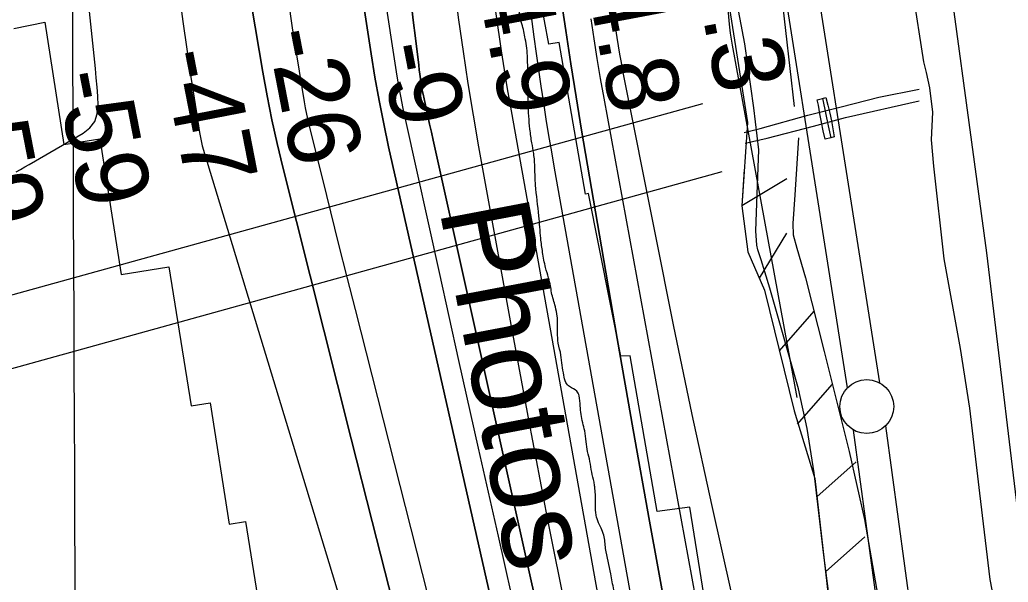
# Model space of a CAD drawing. Extents: x 3419139 to 3457078, y 540382 to 565875.
# Drawn here: x 3439010 to 3439927, y 554398 to 554920 of the extents above; entities that cross this region are included whole.
import ezdxf

# ---------------------------------------------------------------- set-up
doc = ezdxf.new("R2010")
doc.units = 0
for name, color, linetype in [('V-BRDG-OTLN', 7, 'Continuous'), ('V-FLOD-BASE', 7, 'Continuous'), ('V-GRID-MAJR', 7, 'Continuous'), ('V-LEVE-TOET', 7, 'Continuous'), ('V-RIVR-EDGE', 7, 'Continuous'), ('V-RIVR-IDEN', 7, 'Continuous'), ('V-RIVR-RANG', 7, 'Continuous'), ('V-ROAD-CNTR', 7, 'Continuous'), ('V-RRAP-FSHR', 7, 'Continuous'), ('V-RRAP-RVMT', 7, 'Continuous'), ('V-SURV-LINE', 7, 'Continuous'), ('V-TOPO-DPTH', 7, 'Continuous'), ('V-TOPO-MAJR', 7, 'Continuous'), ('V-TOPO-MINR', 7, 'Continuous'), ('V-TOPO-WATR', 7, 'Continuous'), ('V-UTIL-LINE', 7, 'Continuous')]:
    doc.layers.add(name, color=color, linetype=linetype)

msp = doc.modelspace()

# ---------------------------------------------------------------- linework, layer by layer
at = {"layer": 'V-BRDG-OTLN'}
msp.add_lwpolyline([(3439749.87, 554845.8), (3439754.63, 554847.01), (3439757.82, 554847.83), (3439759.7, 554840.62), (3439761.41, 554833.37), (3439762.93, 554826.08), (3439764.28, 554818.75), (3439765.44, 554811.4), (3439762.43, 554810.57), (3439757.26, 554809.14), (3439755.44, 554817.01), (3439753.79, 554824.91), (3439752.31, 554832.84), (3439750.99, 554840.8)], close=True, dxfattribs=at)
msp.add_lwpolyline([(3439754.63, 554847.01), (3439754.86, 554845.79), (3439757.33, 554833.62), (3439759.95, 554821.47), (3439762.43, 554810.57)], dxfattribs=at)
at = {"layer": 'V-FLOD-BASE'}
for points in [[(3439602.39, 555940.97), (3439610.62, 555860.66), (3439621.65, 555775.29), (3439629.34, 555701.72), (3439639.26, 555619.16), (3439647.18, 555526.78), (3439660.71, 555427.09), (3439668.04, 555323.21), (3439677.09, 555228.58), (3439688.38, 555137.32), (3439702.48, 555045.2), (3439712.16, 554980.61), (3439720.42, 554909.85), (3439728.39, 554839.37)], [(3439732.26, 554810.44), (3439729.04, 554757.67), (3439727.3, 554731.01), (3439727.56, 554720.62), (3439730.89, 554708.26), (3439738.97, 554680.73), (3439756.22, 554612.19), (3439779.58, 554519.49), (3439793.75, 554456.58), (3439805.94, 554385.24), (3439813.65, 554321.78), (3439825.79, 554230.52), (3439838.21, 554139.53), (3439850.64, 554050.23), (3439861.12, 553972.72), (3439871.35, 553905.32)]]:
    msp.add_lwpolyline(points, dxfattribs=at)
at = {"layer": 'V-GRID-MAJR'}
msp.add_spline([(3439098.77, 545841.13), (3439072.33, 551898.65), (3439045.89, 557959.64), (3439019.44, 564020.65), (3439019.42, 564024.1)], degree=3, dxfattribs=at)
at = {"layer": 'V-LEVE-TOET'}
for points in [[(3439831.14, 553904.45), (3439824, 553965.54), (3439807.98, 554065.87), (3439797.52, 554142.09), (3439784.54, 554226.44), (3439774.35, 554298.74), (3439763.02, 554368.52), (3439755.6, 554425.97), (3439747.08, 554499.67), (3439740.46, 554540.86), (3439732.42, 554577.58), (3439715.19, 554638.69), (3439705.74, 554670.93), (3439701.02, 554686.07), (3439697.68, 554697.28), (3439694.62, 554706.53), (3439693.79, 554711.01), (3439692.7, 554724.18), (3439694.18, 554758.08), (3439695.68, 554799.26), (3439691, 554838.2), (3439682.74, 554897.61), (3439664.2, 554994.02)], [(3439838.15, 554946.85), (3439848.36, 554881), (3439850.86, 554871.19), (3439853.91, 554856.89), (3439856.66, 554834.2), (3439855.48, 554808.7), (3439857.66, 554784.05), (3439867.27, 554698.3), (3439882.48, 554615.07), (3439891.04, 554559.86), (3439900.38, 554480.84), (3439910, 554400.98), (3439924.39, 554327.55), (3439935.64, 554224.99)]]:
    msp.add_lwpolyline(points, dxfattribs=at)
at = {"layer": 'V-RIVR-EDGE'}
for points in [[(3439543.91, 554480), (3439543.32, 554486.69), (3439542.62, 554491.27), (3439540.53, 554500.44), (3439538.8, 554510.31), (3439536.7, 554519.47), (3439535.32, 554528.64), (3439533.93, 554538.86), (3439532.19, 554546.27), (3439529.76, 554561.78), (3439528.73, 554571.29), (3439526.62, 554575.53), (3439519.94, 554579.77), (3439516.43, 554583.66), (3439514.68, 554590.36), (3439512.94, 554599.52), (3439511.91, 554609.04), (3439509.47, 554619.97), (3439508.79, 554629.84), (3439508.81, 554638.65), (3439508.47, 554644.99), (3439506.73, 554653.8), (3439503.24, 554666.85), (3439502.2, 554673.19), (3439500.46, 554680.6), (3439497.66, 554690.12), (3439494.88, 554704.22), (3439493.15, 554717.26), (3439491.44, 554738.06), (3439488.34, 554766.61), (3439487.67, 554782.47), (3439486.65, 554795.86), (3439484.91, 554805.73), (3439483.18, 554818.42), (3439481.48, 554842.74), (3439481.52, 554860), (3439481.19, 554870.93), (3439480.87, 554884.32), (3439480.19, 554893.48), (3439478.8, 554902.3), (3439475.67, 554916.05), (3439473.57, 554924.51), (3439473.58, 554928.03), (3439475.36, 554932.61), (3439475.36, 554936.13), (3439473.96, 554938.96), (3439472.21, 554942.84), (3439468.7, 554949.54), (3439467.66, 554955.53), (3439467.67, 554961.52), (3439467, 554972.45), (3439467.01, 554977.38), (3439467.02, 554983.37), (3439465.97, 554986.55), (3439461.77, 554994.66), (3439459.32, 555002.77), (3439456.9, 555022.51), (3439457.63, 555031.67), (3439457.64, 555035.55), (3439456.94, 555039.78), (3439454.14, 555047.18), (3439453.1, 555052.82), (3439453.11, 555056), (3439454.53, 555059.16), (3439453.14, 555068.33), (3439453.86, 555076.08), (3439453.52, 555080.66), (3439450.39, 555096.17), (3439448.68, 555116.26), (3439447.65, 555127.54), (3439446.25, 555134.24), (3439444.5, 555138.47), (3439444.51, 555141.64), (3439444.52, 555145.52), (3439443.13, 555152.22), (3439438.59, 555168.44), (3439435.44, 555180.08), (3439433, 555189.24), (3439430.55, 555195.24), (3439427.41, 555209.69), (3439426.07, 555235.42), (3439423.3, 555257.98), (3439423.34, 555271.02), (3439423.35, 555275.95), (3439425.12, 555280.18), (3439424.78, 555283.7), (3439423.06, 555303.08), (3439422.03, 555311.9), (3439421.02, 555332.34), (3439420.69, 555340.79)], [(3439897.96, 552838.81), (3439895.18, 552852.91), (3439892.04, 552868.07), (3439889.26, 552883.93), (3439888.92, 552888.51), (3439886.81, 552890.99), (3439885.41, 552893.46), (3439884.71, 552896.28), (3439883.69, 552908.96), (3439881.25, 552919.89), (3439878.81, 552931.18), (3439877.42, 552939.99), (3439873.94, 552955.15), (3439875, 552957.61), (3439875.01, 552962.55), (3439873.97, 552969.24), (3439873.63, 552972.77), (3439870.47, 552980.18), (3439865.91, 552986.88), (3439863.81, 552992.53), (3439861.36, 552999.93), (3439860.32, 553005.57), (3439858.57, 553011.92), (3439857.18, 553017.91), (3439855.43, 553023.91), (3439852.28, 553031.32), (3439848.77, 553037.32), (3439845.62, 553045.08), (3439842.12, 553056.71), (3439838.28, 553071.17), (3439833.75, 553092.32), (3439828.87, 553114.18), (3439822.92, 553128.29), (3439821.87, 553133.93), (3439821.89, 553141.33), (3439820.5, 553150.5), (3439817.01, 553162.14), (3439815.97, 553169.89), (3439815.3, 553181.87), (3439812.88, 553202.32), (3439811.84, 553208.31), (3439810.44, 553213.6), (3439806.59, 553223.12), (3439803.44, 553233), (3439801.01, 553245.69), (3439798.2, 553251.33), (3439796.45, 553255.21), (3439794.35, 553261.56), (3439791.93, 553279.19), (3439786.69, 553298.23), (3439783.91, 553315.15), (3439782.87, 553320.08), (3439780.07, 553329.96), (3439779.04, 553338.42), (3439778, 553346.17), (3439774.51, 553358.87), (3439769.61, 553372.27), (3439764.01, 553387.79), (3439758.06, 553404.36), (3439752.81, 553419.53), (3439741.6, 553446.34), (3439736.69, 553454.1), (3439731.43, 553464.68), (3439730.38, 553469.97), (3439729.69, 553476.67), (3439729.72, 553486.54), (3439729.02, 553489), (3439726.91, 553492.18), (3439726.23, 553498.88), (3439724.85, 553513.68), (3439721.37, 553531.31), (3439717.55, 553552.81), (3439712.31, 553570.44), (3439710.22, 553579.61), (3439708.49, 553593.71), (3439705.02, 553614.16), (3439704.68, 553622.26), (3439704.69, 553626.49), (3439708.58, 553631.06), (3439711.06, 553635.28), (3439710.71, 553638.81), (3439709.32, 553643.75), (3439705.8, 553645.87), (3439697.71, 553653.64), (3439695.61, 553658.93), (3439695.27, 553664.92), (3439694.61, 553680.43), (3439696.73, 553685.01), (3439699.56, 553689.23), (3439699.22, 553692.75), (3439697.12, 553699.8), (3439696.09, 553710.03), (3439696.11, 553716.37), (3439695.45, 553735.75), (3439695.83, 553748.79), (3439695.16, 553762.53), (3439697.64, 553766.75), (3439697.65, 553771.33), (3439696.97, 553779.09), (3439694.87, 553788.26), (3439690.34, 553807.65), (3439684.39, 553823.52), (3439683.35, 553830.57), (3439684.77, 553836.2), (3439684.08, 553840.79), (3439681.63, 553846.78), (3439678.83, 553854.89), (3439676.03, 553862.3), (3439673.95, 553876.4), (3439675.37, 553880.98), (3439676.44, 553885.56), (3439676.45, 553890.84), (3439674, 553896.84), (3439671.54, 553900.02), (3439667.69, 553908.13), (3439664.21, 553925.76), (3439659.68, 553946.21), (3439656.87, 553950.09), (3439654.77, 553956.44), (3439651.65, 553979.7), (3439648.52, 553996.27), (3439644.69, 554015.66), (3439637.35, 554038.94), (3439632.82, 554059.03), (3439619.2, 554107.34), (3439614.67, 554128.14), (3439609.11, 554159.87), (3439602.52, 554201.12), (3439596.58, 554223.33), (3439592.76, 554245.19), (3439591.04, 554261.75), (3439592.85, 554281.83), (3439596.05, 554295.22), (3439598.2, 554308.6), (3439596.46, 554318.12), (3439590.5, 554329.41), (3439580.32, 554345.64), (3439576.45, 554348.47), (3439571.87, 554348.84), (3439568.35, 554349.55), (3439562.36, 554351.33), (3439561.32, 554354.85), (3439560.97, 554358.03), (3439560.98, 554363.31), (3439562.76, 554369.65), (3439563.84, 554378.46), (3439561.05, 554391.15), (3439558.27, 554405.96), (3439553.4, 554429.58), (3439551.66, 554441.91), (3439549.21, 554448.61), (3439546.76, 554453.55), (3439544.66, 554460.61), (3439543.98, 554469.77), (3439544, 554477.88), (3439543.91, 554480)]]:
    msp.add_spline(points, degree=3, dxfattribs=at)
at = {"layer": 'V-ROAD-CNTR'}
msp.add_lwpolyline([(3439745.28, 555940.99), (3439774.07, 555755.39), (3439795.91, 555569.54), (3439825.13, 555319.06), (3439860.14, 555048.4), (3439906.86, 554703.78), (3439941.84, 554412.72), (3439958.71, 554295.03), (3439968.64, 554203.99), (3439976.22, 554134.65), (3439991.11, 554047.64), (3440004.28, 553962.83), (3440019.06, 553859.33), (3440056.36, 553679.63), (3440125.65, 553360.46), (3440179.2, 553136.93), (3440245.78, 552840.69)], dxfattribs=at)
at = {"layer": 'V-RRAP-FSHR'}
for p, q in [((3439679.83, 554747.6), (3439721.64, 554772.83)), ((3439696.06, 554680.21), (3439721.44, 554721.92)), ((3439714.69, 554612.89), (3439746.88, 554649.61)), ((3439731.34, 554544.9), (3439763.53, 554581.62)), ((3439749.38, 554477.49), (3439785.92, 554509.89)), ((3439757.38, 554407.95), (3439793.92, 554440.35))]:
    msp.add_line(p, q, dxfattribs=at)
for points in [[(3439522.98, 556207.72), (3439541.36, 556021.46), (3439583.01, 555683.8), (3439624.13, 555273.38), (3439659.87, 554983.57), (3439685.08, 554824.69), (3439679.82, 554747.46), (3439685.29, 554704.76), (3439700.93, 554669.09), (3439728.32, 554557.22), (3439747.43, 554494.51), (3439772.64, 554275.32), (3439797.96, 554116.78), (3439825.34, 553912.33), (3439849.7, 553822.93), (3439865.11, 553645.02), (3439856.59, 553600.9), (3439862.35, 553565.71), (3439888.28, 553542.26), (3439924.45, 553445.47), (3439970.85, 553198.92), (3440071.23, 552762.47), (3440155.84, 552373.79)], [(3439682.11, 554781.1), (3439679.82, 554747.46), (3439685.29, 554704.76), (3439700.93, 554669.09), (3439728.32, 554557.22), (3439747.43, 554494.51), (3439772.64, 554275.32), (3439773.57, 554269.54)]]:
    msp.add_lwpolyline(points, dxfattribs=at)
at = {"layer": 'V-RRAP-RVMT'}
for p, q in [((3439500.56, 554897.24), (3439476.57, 555029.82)), ((3439004.07, 554911.72), (3439032.73, 554917.74)), ((3439032.73, 554917.74), (3439050.62, 554804.21)), ((3439510.17, 554898.87), (3439500.56, 554897.24)), ((3439534.59, 554758.23), (3439510.17, 554898.87)), ((3439050.62, 554804.21), (3439083.78, 554809.42)), ((3439083.78, 554809.42), (3439103.74, 554683.84)), ((3439537.42, 554758.95), (3439534.59, 554758.23)), ((3439567.61, 554607.84), (3439537.42, 554758.95)), ((3439103.74, 554683.84), (3439148.04, 554690.95)), ((3439148.04, 554690.95), (3439168.59, 554561.9)), ((3439576.07, 554608.4), (3439567.61, 554607.84)), ((3439601.35, 554463.95), (3439576.07, 554608.4)), ((3439168.59, 554561.9), (3439186.24, 554564.67)), ((3439186.24, 554564.67), (3439204, 554452.16)), ((3439631.56, 554467.84), (3439601.35, 554463.95)), ((3439679.39, 554168.49), (3439631.56, 554467.84)), ((3439204, 554452.16), (3439219.16, 554454.62)), ((3439219.16, 554454.62), (3439239.75, 554324.66))]:
    msp.add_line(p, q, dxfattribs=at)
at = {"layer": 'V-SURV-LINE'}
for points in [[(3439777.82, 554578.66), (3439693.98, 555110.02)], [(3439723.61, 555114.68), (3439807.46, 554583.33)], [(3439859.95, 553976.63), (3439783.58, 554539.44)], [(3439813.31, 554543.47), (3439889.68, 553980.66)]]:
    msp.add_lwpolyline(points, dxfattribs=at)
msp.add_circle((3439795.76, 554561.26), 25, dxfattribs=at)
at = {"layer": 'V-TOPO-DPTH'}
for points in [[(3439203.43, 555059.91), (3439235.29, 554871.43), (3439239.31, 554849.29), (3439243.67, 554827.23), (3439248.56, 554805.27), (3439253.8, 554783.38), (3439317.33, 554531.21), (3439336.69, 554454.71), (3439356.15, 554378.23), (3439375.77, 554301.8), (3439395.5, 554225.4), (3439426.86, 554104.48), (3439430.86, 554088.52), (3439434.69, 554072.53), (3439438.27, 554056.47), (3439441.68, 554040.37), (3439463.36, 553933.74)], [(3439463.36, 553933.74), (3439441.68, 554040.37), (3439438.27, 554056.47), (3439434.69, 554072.53), (3439430.86, 554088.52), (3439426.86, 554104.48), (3439395.5, 554225.4), (3439375.77, 554301.8), (3439356.15, 554378.23), (3439336.69, 554454.71), (3439317.33, 554531.21), (3439253.8, 554783.38), (3439248.56, 554805.27), (3439243.67, 554827.23), (3439239.31, 554849.29), (3439235.29, 554871.43), (3439203.43, 555059.91)], [(3439545.27, 553938.31), (3439539.18, 553968.37), (3439533.02, 553998.41), (3439526.81, 554028.44), (3439517.11, 554075.09), (3439515.69, 554081.78), (3439514.25, 554088.47), (3439512.75, 554095.15), (3439511.23, 554101.83), (3439494.63, 554173.4), (3439484.82, 554215.86), (3439475.06, 554258.33), (3439465.37, 554300.82), (3439455.72, 554343.32), (3439351.98, 554802.09), (3439347.37, 554823.55), (3439343.06, 554845.07), (3439339.2, 554866.68), (3439335.65, 554888.34), (3439314.36, 555027.46)], [(3439314.36, 555027.46), (3439335.65, 554888.34), (3439339.2, 554866.68), (3439343.06, 554845.07), (3439347.37, 554823.55), (3439351.98, 554802.09), (3439455.72, 554343.32), (3439465.37, 554300.82), (3439475.06, 554258.33), (3439484.82, 554215.86), (3439494.63, 554173.4), (3439511.23, 554101.83), (3439512.75, 554095.15), (3439514.25, 554088.47), (3439515.69, 554081.78), (3439517.11, 554075.09), (3439526.81, 554028.44), (3439533.02, 553998.41), (3439539.18, 553968.37), (3439545.27, 553938.31)], [(3439632.19, 553926.82), (3439620.35, 553986.21), (3439597.32, 554103.01), (3439596.92, 554105.04), (3439596.72, 554106.06), (3439596.52, 554107.08), (3439594.64, 554116.78), (3439593.52, 554122.65), (3439592.41, 554128.52), (3439591.32, 554134.4), (3439590.26, 554140.29), (3439464.41, 554844.08), (3439462.37, 554855.83), (3439460.41, 554867.59), (3439458.57, 554879.37), (3439456.81, 554891.16), (3439446.89, 554960.06)], [(3439632.19, 553926.82), (3439620.35, 553986.21), (3439597.32, 554103.01), (3439596.92, 554105.04), (3439596.72, 554106.06), (3439596.52, 554107.08), (3439594.64, 554116.78), (3439593.52, 554122.65), (3439592.41, 554128.52), (3439591.32, 554134.4), (3439590.26, 554140.29), (3439464.41, 554844.08), (3439462.37, 554855.83), (3439460.41, 554867.59), (3439458.57, 554879.37), (3439456.81, 554891.16), (3439446.89, 554960.06)], [(3439578.87, 553554.05), (3439480.37, 554015.22), (3439473.38, 554047.05), (3439466.14, 554078.82), (3439458.53, 554110.5), (3439450.68, 554142.12), (3439321.07, 554651.19), (3439313.42, 554681.38), (3439305.81, 554711.58), (3439298.27, 554741.79), (3439290.77, 554772.02), (3439278.6, 554821.27), (3439277.28, 554826.89), (3439276.05, 554832.53), (3439274.95, 554838.19), (3439273.94, 554843.88), (3439267, 554885.72), (3439262.85, 554912.37), (3439259.05, 554939.07)], [(3439578.87, 553554.05), (3439480.37, 554015.22), (3439473.38, 554047.05), (3439466.14, 554078.82), (3439458.53, 554110.5), (3439450.68, 554142.12), (3439321.07, 554651.19), (3439313.42, 554681.38), (3439305.81, 554711.58), (3439298.27, 554741.79), (3439290.77, 554772.02), (3439278.6, 554821.27), (3439277.28, 554826.89), (3439276.05, 554832.53), (3439274.95, 554838.19), (3439273.94, 554843.88), (3439267, 554885.72), (3439262.85, 554912.37), (3439259.05, 554939.07)], [(3439372.86, 554936.32), (3439374.86, 554919.59), (3439376.88, 554902.87), (3439379.92, 554877.74), (3439380.45, 554873.58), (3439381, 554869.42), (3439381.6, 554865.27), (3439382.23, 554861.12), (3439383.23, 554854.74), (3439383.75, 554851.89), (3439383.94, 554850.95), (3439386.75, 554837.97), (3439388.36, 554830.54), (3439389.98, 554823.12), (3439391.62, 554815.69), (3439393.26, 554808.27), (3439540.61, 554146.82), (3439546.21, 554121.41), (3439551.72, 554095.98), (3439557.13, 554070.53), (3439562.45, 554045.07), (3439614.25, 553794.32)], [(3439372.86, 554936.32), (3439374.86, 554919.59), (3439376.88, 554902.87), (3439379.92, 554877.74), (3439380.45, 554873.58), (3439381, 554869.42), (3439381.6, 554865.27), (3439382.23, 554861.12), (3439383.23, 554854.74), (3439383.75, 554851.89), (3439383.94, 554850.95), (3439386.75, 554837.97), (3439388.36, 554830.54), (3439389.98, 554823.12), (3439391.62, 554815.69), (3439393.26, 554808.27), (3439540.61, 554146.82), (3439546.21, 554121.41), (3439551.72, 554095.98), (3439557.13, 554070.53), (3439562.45, 554045.07), (3439614.25, 553794.32)], [(3439511.82, 554940.94), (3439516.32, 554910.06), (3439520.99, 554879.2), (3439525.93, 554848.39), (3439531.06, 554817.6), (3439549.57, 554709.36), (3439564.22, 554624.49), (3439579.05, 554539.66), (3439594.14, 554454.88), (3439609.42, 554370.13), (3439645.17, 554173.51), (3439650.33, 554145.15), (3439655.48, 554116.78), (3439660.63, 554088.41), (3439665.77, 554060.04), (3439699.55, 553873.72)]]:
    msp.add_lwpolyline(points, dxfattribs=at)
at = {"layer": 'V-TOPO-MAJR'}
for points in [[(3439731.16, 554569.74), (3439671.02, 554896.52), (3439670.08, 554902.08), (3439669.25, 554907.65), (3439668.58, 554913.24), (3439668.02, 554918.85), (3439666.38, 554938.05), (3439665.05, 554953.27), (3439663.7, 554968.49), (3439662.29, 554983.7), (3439660.85, 554998.91), (3439651.13, 555100)], [(3439157.4, 554944.04), (3439160.94, 554918.28), (3439164.65, 554892.55), (3439168.47, 554866.83), (3439174.4, 554827.79), (3439175.4, 554821.62), (3439176.47, 554815.45), (3439177.65, 554809.31), (3439178.91, 554803.18), (3439383.96, 554128.95)]]:
    msp.add_lwpolyline(points, dxfattribs=at)
at = {"layer": 'V-TOPO-MINR'}
for points in [[(3439006.21, 554778.94), (3439010.2, 554781.22), (3439014.19, 554783.5), (3439018.17, 554785.79), (3439068.53, 554814.82), (3439074.55, 554819.86), (3439079.12, 554825.69), (3439081.53, 554832.7), (3439082.48, 554840.49), (3439081.96, 554849.04), (3439081.36, 554857.59), (3439080.62, 554866.12), (3439079.79, 554874.65), (3439033.93, 555309.56), (3439028.27, 555361.34), (3439022.37, 555413.09), (3439016.09, 555464.8), (3439009.56, 555516.48)], [(3439663.98, 553908.32), (3439654.24, 553958.91), (3439644.72, 554009.54), (3439639.16, 554039.67), (3439632.61, 554075.28), (3439626.11, 554110.89), (3439619.67, 554146.52), (3439613.27, 554182.15), (3439506.01, 554782.35), (3439503.36, 554797.51), (3439500.77, 554812.69), (3439498.29, 554827.87), (3439495.87, 554843.07), (3439493.57, 554858.29), (3439491.34, 554873.52), (3439489.21, 554888.76), (3439487.17, 554904.02), (3439417.47, 555437.48)], [(3439683.32, 553554.14), (3439587.45, 554028.26), (3439580.14, 554064.24), (3439572.79, 554100.21), (3439565.37, 554136.16), (3439557.91, 554172.11), (3439535.64, 554278.94), (3439517.35, 554368.37), (3439499.53, 554457.88), (3439482.39, 554547.53), (3439465.72, 554637.27), (3439435.74, 554802.15), (3439430.62, 554831.51), (3439425.79, 554860.92), (3439421.39, 554890.4), (3439417.27, 554919.92), (3439395.69, 555083.5)], [(3439203.43, 555059.91), (3439235.29, 554871.43), (3439239.31, 554849.29), (3439243.67, 554827.23), (3439248.56, 554805.27), (3439253.8, 554783.38), (3439317.33, 554531.21), (3439336.69, 554454.71), (3439356.15, 554378.23), (3439375.77, 554301.8), (3439395.5, 554225.4), (3439426.86, 554104.48), (3439430.86, 554088.52), (3439434.69, 554072.53), (3439438.27, 554056.47), (3439441.68, 554040.37), (3439463.36, 553933.74)], [(3439545.27, 553938.31), (3439539.18, 553968.37), (3439533.02, 553998.41), (3439526.81, 554028.44), (3439517.11, 554075.09), (3439515.69, 554081.78), (3439514.25, 554088.47), (3439512.75, 554095.15), (3439511.23, 554101.83), (3439494.63, 554173.4), (3439484.82, 554215.86), (3439475.06, 554258.33), (3439465.37, 554300.82), (3439455.72, 554343.32), (3439351.98, 554802.09), (3439347.37, 554823.55), (3439343.06, 554845.07), (3439339.2, 554866.68), (3439335.65, 554888.34), (3439314.36, 555027.46)], [(3439767.7, 553934), (3439754.96, 553999.87), (3439735.27, 554099.53), (3439732.05, 554115.5), (3439728.72, 554131.45), (3439725.26, 554147.37), (3439721.7, 554163.28), (3439670.53, 554387.3), (3439651.92, 554470.47), (3439633.8, 554553.75), (3439616.42, 554637.18), (3439599.52, 554720.71), (3439569.5, 554872.58), (3439568.04, 554880.27), (3439566.64, 554887.97), (3439565.35, 554895.69), (3439564.13, 554903.42), (3439556.79, 554952.07)], [(3439562.83, 553948.96), (3439539.79, 554060.08), (3439536.41, 554076.16), (3439532.97, 554092.22), (3439529.43, 554108.27), (3439525.83, 554124.3), (3439472.3, 554359.44), (3439453.82, 554440.96), (3439435.44, 554522.5), (3439417.2, 554604.07), (3439399.06, 554685.66), (3439367.87, 554826.5), (3439365.5, 554837.71), (3439363.27, 554848.95), (3439361.26, 554860.23), (3439359.38, 554871.53), (3439347.7, 554946.44)], [(3439578.87, 553554.05), (3439480.37, 554015.22), (3439473.38, 554047.05), (3439466.14, 554078.82), (3439458.53, 554110.5), (3439450.68, 554142.12), (3439321.07, 554651.19), (3439313.42, 554681.38), (3439305.81, 554711.58), (3439298.27, 554741.79), (3439290.77, 554772.02), (3439278.6, 554821.27), (3439277.28, 554826.89), (3439276.05, 554832.53), (3439274.95, 554838.19), (3439273.94, 554843.88), (3439267, 554885.72), (3439262.85, 554912.37), (3439259.05, 554939.07)], [(3439614.25, 553794.32), (3439562.45, 554045.07), (3439557.13, 554070.53), (3439551.72, 554095.98), (3439546.21, 554121.41), (3439540.61, 554146.82), (3439393.26, 554808.27), (3439391.62, 554815.69), (3439389.98, 554823.12), (3439388.36, 554830.54), (3439386.75, 554837.97), (3439383.94, 554850.95), (3439383.75, 554851.89), (3439383.23, 554854.74), (3439382.23, 554861.12), (3439381.6, 554865.27), (3439381, 554869.42), (3439380.45, 554873.58), (3439379.92, 554877.74), (3439376.88, 554902.87), (3439374.86, 554919.59), (3439372.86, 554936.32)], [(3439699.55, 553873.72), (3439665.77, 554060.04), (3439660.63, 554088.41), (3439655.48, 554116.78), (3439650.33, 554145.15), (3439645.17, 554173.51), (3439609.42, 554370.13), (3439594.14, 554454.88), (3439579.05, 554539.66), (3439564.22, 554624.49), (3439549.57, 554709.36), (3439531.06, 554817.6), (3439525.93, 554848.39), (3439520.99, 554879.2), (3439516.32, 554910.06), (3439511.82, 554940.94)], [(3439782.38, 553576.14), (3439696.25, 554060.41), (3439690.68, 554091.56), (3439685.06, 554122.71), (3439679.38, 554153.84), (3439673.65, 554184.97), (3439667.89, 554216.09), (3439662.14, 554247.21), (3439656.42, 554278.34), (3439650.7, 554309.47), (3439552.01, 554847.28), (3439548.74, 554865.59), (3439545.6, 554883.93), (3439542.65, 554902.3), (3439539.82, 554920.69)]]:
    msp.add_lwpolyline(points, dxfattribs=at)
at = {"layer": 'V-TOPO-WATR'}
msp.add_lwpolyline([(3439632.19, 553926.82), (3439620.35, 553986.21), (3439597.32, 554103.01), (3439596.92, 554105.04), (3439596.72, 554106.06), (3439596.52, 554107.08), (3439594.64, 554116.78), (3439593.52, 554122.65), (3439592.41, 554128.52), (3439591.32, 554134.4), (3439590.26, 554140.29), (3439464.41, 554844.08), (3439462.37, 554855.83), (3439460.41, 554867.59), (3439458.57, 554879.37), (3439456.81, 554891.16), (3439446.89, 554960.06)], dxfattribs=at)
at = {"layer": 'V-UTIL-LINE'}
for p, q in [((3437078.02, 554131.72), (3439643.59, 554842.43)), ((3437096.11, 554068.4), (3439661.69, 554779.11))]:
    msp.add_line(p, q, dxfattribs=at)
for points in [[(3439681.9, 554815.3), (3439696.89, 554819.13), (3439741.21, 554831.52), (3439772.11, 554839.16), (3439807.1, 554848.17), (3439844.36, 554855.57)], [(3439683.01, 554805.53), (3439703.46, 554810.25), (3439746.4, 554821.28), (3439776.17, 554829.39), (3439844.34, 554844.67)]]:
    msp.add_lwpolyline(points, dxfattribs=at)

# ---------------------------------------------------------------- texts
at = {"layer": 'V-RIVR-IDEN'}
msp.add_text(' Photos', height=83, rotation=280.75568, dxfattribs=at).set_placement((3439393.17, 554774.62))
at = {"layer": 'V-RIVR-RANG'}
for s, rotation, p in [('26.3', 280.71833, (3439625.06, 555020.14)), ('24.8', 280.71833, (3439526.85, 555001.29)), ('4.9', 280.71833, (3439434.77, 554950.05)), ('-26', 281.0045, (3439238.78, 554907.97)), ('-9', 281.0045, (3439343.18, 554894.97)), ('-47', 281.0045, (3439140.67, 554888.61)), ('-59', 281.0045, (3439042.61, 554868.98)), ('-59', 281.0045, (3438944.4, 554850.14))]:
    msp.add_text(s, height=67, rotation=rotation, dxfattribs=at).set_placement(p)

doc.saveas('drawing.dxf')
